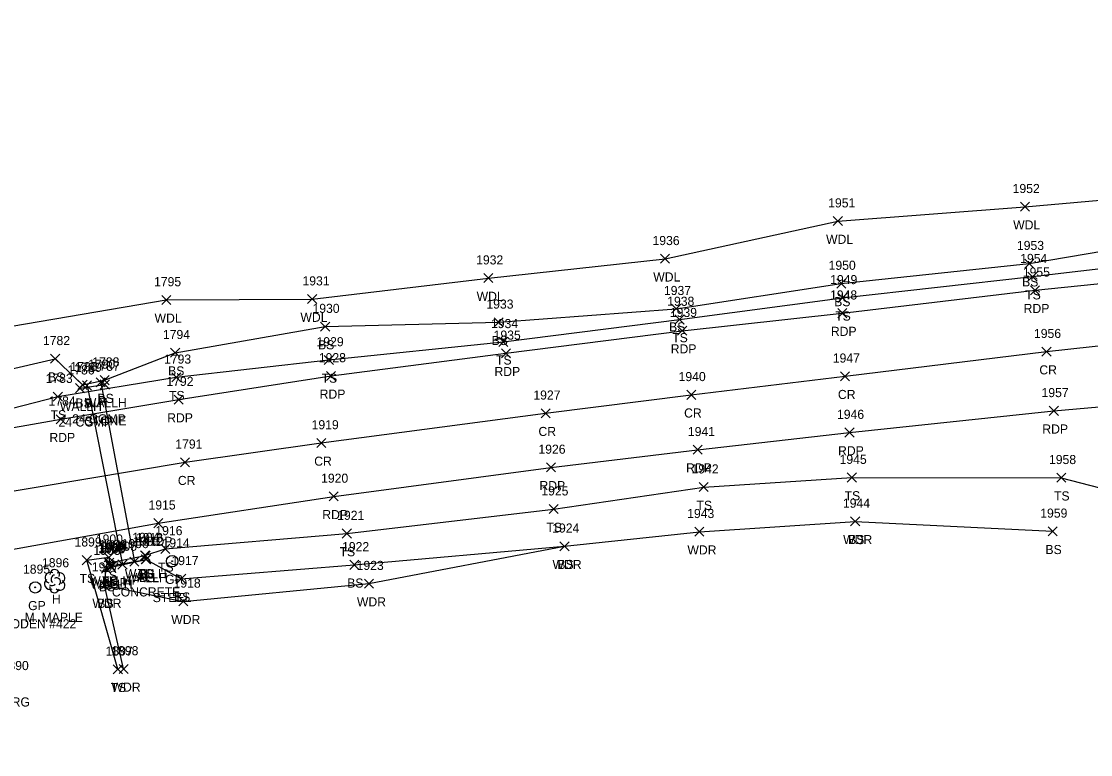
# Model space of a CAD drawing. Extents: x 1611797 to 1633212, y 298978 to 305475.
# Drawn here: x 1613918.9 to 1614153.6, y 301336.2 to 301497.2 of the extents above; entities that cross this region are included whole.
import ezdxf

# ---------------------------------------------------------------- set-up
doc = ezdxf.new("R2010")
doc.units = 0
for name, color, linetype in [('D_A', 7, 'Continuous'), ('D_C', 7, 'Continuous'), ('D_I', 7, 'Continuous'), ('D_TIC', 7, 'Continuous'), ('DCP', 7, 'Continuous'), ('DHW', 7, 'Continuous'), ('L_A', 7, 'Continuous'), ('L_C', 7, 'Continuous'), ('L_I', 7, 'Continuous'), ('L_TIC', 7, 'Continuous'), ('LAWA', 7, 'Continuous'), ('LELB', 7, 'Continuous'), ('LTD', 7, 'Continuous'), ('P_A', 7, 'Continuous'), ('P_I', 7, 'Continuous'), ('P_TIC', 7, 'Continuous'), ('PET', 7, 'Continuous'), ('PRC', 7, 'Continuous'), ('R_A', 7, 'Continuous'), ('R_C', 7, 'Continuous'), ('R_I', 7, 'Continuous'), ('RGP', 7, 'Continuous')]:
    doc.layers.add(name, color=color, linetype=linetype)

msp = doc.modelspace()

# ---------------------------------------------------------------- linework, layer by layer
at = {"layer": 'D_TIC'}
for points in [[(1613930.74, 301415.69), (1613932.74, 301417.69)], [(1613932.74, 301415.69), (1613930.74, 301417.69)], [(1613932.29, 301416.26), (1613934.29, 301418.26)], [(1613934.29, 301416.26), (1613932.29, 301418.26)], [(1613935.3, 301416.95), (1613937.3, 301418.95)], [(1613937.3, 301416.95), (1613935.3, 301418.95)], [(1613936.2, 301416.49), (1613938.2, 301418.49)], [(1613938.2, 301416.49), (1613936.2, 301418.49)], [(1613937.18, 301377.35), (1613939.18, 301379.35)], [(1613939.18, 301377.35), (1613937.18, 301379.35)], [(1613937.18, 301377.35), (1613939.18, 301379.35)], [(1613939.18, 301377.35), (1613937.18, 301379.35)], [(1613942.68, 301377.55), (1613944.68, 301379.55)], [(1613944.68, 301377.55), (1613942.68, 301379.55)], [(1613944.99, 301378.93), (1613946.99, 301380.93)], [(1613946.99, 301378.93), (1613944.99, 301380.93)], [(1613944.99, 301378.93), (1613946.99, 301380.93)], [(1613946.99, 301378.93), (1613944.99, 301380.93)], [(1613945.19, 301378.07), (1613947.19, 301380.07)], [(1613947.19, 301378.07), (1613945.19, 301380.07)], [(1613937.46, 301376.65), (1613939.46, 301378.65)], [(1613939.46, 301376.65), (1613937.46, 301378.65)], [(1613940.07, 301376.96), (1613942.07, 301378.96)], [(1613942.07, 301376.96), (1613940.07, 301378.96)]]:
    msp.add_lwpolyline(points, dxfattribs=at)
at = {"layer": 'DCP'}
for points in [[(1613933.29, 301417.26), (1613941.07, 301377.96)], [(1613936.3, 301417.95), (1613943.68, 301378.55)]]:
    msp.add_lwpolyline(points, dxfattribs=at)
at = {"layer": 'DHW'}
for points in [[(1613931.74, 301416.69), (1613937.2, 301417.49)], [(1613938.18, 301378.35), (1613938.46, 301377.65), (1613946.19, 301379.07), (1613945.99, 301379.93)], [(1613938.18, 301378.35), (1613945.99, 301379.93)]]:
    msp.add_lwpolyline(points, dxfattribs=at)
at = {"layer": 'L_TIC'}
for points in [[(1614138.15, 301455.54), (1614140.15, 301457.54)], [(1614140.15, 301455.54), (1614138.15, 301457.54)], [(1614097.09, 301452.38), (1614099.09, 301454.38)], [(1614099.09, 301452.38), (1614097.09, 301454.38)], [(1614059.15, 301444.11), (1614061.15, 301446.11)], [(1614061.15, 301444.11), (1614059.15, 301446.11)], [(1614139.09, 301443.03), (1614141.09, 301445.03)], [(1614141.09, 301443.03), (1614139.09, 301445.03)], [(1614020.38, 301439.86), (1614022.38, 301441.86)], [(1614022.38, 301439.86), (1614020.38, 301441.86)], [(1614097.84, 301438.68), (1614099.84, 301440.68)], [(1614099.84, 301438.68), (1614097.84, 301440.68)], [(1614139.8, 301440.18), (1614141.8, 301442.18)], [(1614141.8, 301440.18), (1614139.8, 301442.18)], [(1613949.68, 301435.07), (1613951.68, 301437.07)], [(1613951.68, 301435.07), (1613949.68, 301437.07)], [(1613981.7, 301435.25), (1613983.7, 301437.25)], [(1613983.7, 301435.25), (1613981.7, 301437.25)], [(1614098.1, 301435.53), (1614100.1, 301437.53)], [(1614100.1, 301435.53), (1614098.1, 301437.53)], [(1614061.6, 301433.14), (1614063.6, 301435.14)], [(1614063.6, 301433.14), (1614061.6, 301435.14)], [(1613984.55, 301429.21), (1613986.55, 301431.21)], [(1613986.55, 301429.21), (1613984.55, 301431.21)], [(1614022.64, 301430.15), (1614024.64, 301432.15)], [(1614024.64, 301430.15), (1614022.64, 301432.15)], [(1614062.32, 301430.77), (1614064.32, 301432.77)], [(1614064.32, 301430.77), (1614062.32, 301432.77)], [(1614023.64, 301425.87), (1614025.64, 301427.87)], [(1614025.64, 301425.87), (1614023.64, 301427.87)], [(1613925.3, 301422.14), (1613927.3, 301424.14)], [(1613927.3, 301422.14), (1613925.3, 301424.14)], [(1613951.64, 301423.47), (1613953.64, 301425.47)], [(1613953.64, 301423.47), (1613951.64, 301425.47)], [(1613985.36, 301421.88), (1613987.36, 301423.88)], [(1613987.36, 301421.88), (1613985.36, 301423.88)], [(1613936.13, 301417.44), (1613938.13, 301419.44)], [(1613938.13, 301417.44), (1613936.13, 301419.44)], [(1613951.87, 301418.07), (1613953.87, 301420.07)], [(1613953.87, 301418.07), (1613951.87, 301420.07)], [(1613931.29, 301416.42), (1613933.29, 301418.42)], [(1613933.29, 301416.42), (1613931.29, 301418.42)], [(1613925.88, 301413.84), (1613927.88, 301415.84)], [(1613927.88, 301413.84), (1613925.88, 301415.84)], [(1614100.16, 301396.05), (1614102.16, 301398.05)], [(1614102.16, 301396.05), (1614100.16, 301398.05)], [(1614146.12, 301396.01), (1614148.12, 301398.01)], [(1614148.12, 301396.01), (1614146.12, 301398.01)], [(1614067.65, 301393.95), (1614069.65, 301395.95)], [(1614069.65, 301393.95), (1614067.65, 301395.95)], [(1614034.69, 301389.12), (1614036.69, 301391.12)], [(1614036.69, 301389.12), (1614034.69, 301391.12)], [(1614066.7, 301384.15), (1614068.7, 301386.15)], [(1614068.7, 301384.15), (1614066.7, 301386.15)], [(1614100.89, 301386.42), (1614102.89, 301388.42)], [(1614102.89, 301386.42), (1614100.89, 301388.42)], [(1614100.89, 301386.42), (1614102.89, 301388.42)], [(1614102.89, 301386.42), (1614100.89, 301388.42)], [(1614144.21, 301384.24), (1614146.21, 301386.24)], [(1614146.21, 301384.24), (1614144.21, 301386.24)], [(1613989.31, 301383.76), (1613991.31, 301385.76)], [(1613991.31, 301383.76), (1613989.31, 301385.76)], [(1613949.46, 301380.39), (1613951.46, 301382.39)], [(1613951.46, 301380.39), (1613949.46, 301382.39)], [(1614037.09, 301380.96), (1614039.09, 301382.96)], [(1614039.09, 301380.96), (1614037.09, 301382.96)], [(1614037.09, 301380.96), (1614039.09, 301382.96)], [(1614039.09, 301380.96), (1614037.09, 301382.96)], [(1613932.24, 301377.9), (1613934.24, 301379.9)], [(1613934.24, 301377.9), (1613932.24, 301379.9)], [(1613937.07, 301378.55), (1613939.07, 301380.55)], [(1613939.07, 301378.55), (1613937.07, 301380.55)], [(1613937.1, 301377.27), (1613939.1, 301379.27)], [(1613939.1, 301377.27), (1613937.1, 301379.27)], [(1613937.18, 301377.35), (1613939.18, 301379.35)], [(1613939.18, 301377.35), (1613937.18, 301379.35)], [(1613944.99, 301378.93), (1613946.99, 301380.93)], [(1613946.99, 301378.93), (1613944.99, 301380.93)], [(1613945.13, 301378.85), (1613947.13, 301380.85)], [(1613947.13, 301378.85), (1613945.13, 301380.85)], [(1613945.26, 301378.08), (1613947.26, 301380.08)], [(1613947.26, 301378.08), (1613945.26, 301380.08)], [(1613945.26, 301378.08), (1613947.26, 301380.08)], [(1613947.26, 301378.08), (1613945.26, 301380.08)], [(1613936.45, 301376.07), (1613938.45, 301378.07)], [(1613938.45, 301376.07), (1613936.45, 301378.07)], [(1613937.2, 301376.8), (1613939.2, 301378.8)], [(1613939.2, 301376.8), (1613937.2, 301378.8)], [(1613937.56, 301376.4), (1613939.56, 301378.4)], [(1613939.56, 301376.4), (1613937.56, 301378.4)], [(1613990.95, 301376.88), (1613992.95, 301378.88)], [(1613992.95, 301376.88), (1613990.95, 301378.88)], [(1613936.1, 301372.42), (1613938.1, 301374.42)], [(1613938.1, 301372.42), (1613936.1, 301374.42)], [(1613936.1, 301372.42), (1613938.1, 301374.42)], [(1613938.1, 301372.42), (1613936.1, 301374.42)], [(1613952.94, 301373.81), (1613954.94, 301375.81)], [(1613954.94, 301373.81), (1613952.94, 301375.81)], [(1613994.15, 301372.75), (1613996.15, 301374.75)], [(1613996.15, 301372.75), (1613994.15, 301374.75)], [(1613953.4, 301368.86), (1613955.4, 301370.86)], [(1613955.4, 301368.86), (1613953.4, 301370.86)], [(1613939.05, 301353.94), (1613941.05, 301355.94)], [(1613941.05, 301353.94), (1613939.05, 301355.94)], [(1613940.3, 301354.02), (1613942.3, 301356.02)], [(1613942.3, 301354.02), (1613940.3, 301356.02)]]:
    msp.add_lwpolyline(points, dxfattribs=at)
at = {"layer": 'LAWA'}
for points in [[(1613659.39, 301379.3), (1613661.87, 301370.75), (1613686.93, 301375.42), (1613730.09, 301388.72), (1613768.03, 301396.97), (1613816.59, 301404.76), (1613861.02, 301415.83), (1613901.25, 301427.67), (1613950.68, 301436.07), (1613982.7, 301436.25), (1614021.38, 301440.86), (1614060.15, 301445.11), (1614098.09, 301453.38), (1614139.15, 301456.54), (1614173, 301459.52), (1614211.23, 301469.75), (1614243.82, 301473.03), (1614282.31, 301479.54), (1614304.52, 301484.61), (1614323.47, 301484.21), (1614343.41, 301488.74), (1614366.06, 301492.98), (1614391.26, 301497.25)], [(1613941.3, 301355.02), (1613937.1, 301373.42), (1613954.4, 301369.86), (1613995.15, 301373.75), (1614038.09, 301381.96), (1614067.7, 301385.15), (1614101.89, 301387.42)]]:
    msp.add_lwpolyline(points, dxfattribs=at)
at = {"layer": 'LELB'}
for points in [[(1613688.22, 301363.65), (1613727.18, 301373.26), (1613772.17, 301382.86), (1613812.44, 301390.94), (1613866.01, 301400.43), (1613908.89, 301410.23), (1613926.88, 301414.84), (1613952.87, 301419.07), (1613986.36, 301422.88), (1614024.64, 301426.87), (1614063.32, 301431.77), (1614099.1, 301436.53), (1614140.8, 301441.18), (1614173.87, 301445.08), (1614214.29, 301453.13), (1614246.46, 301456.83), (1614285.28, 301461.82), (1614322.04, 301468.56), (1614347.54, 301476.47), (1614359.36, 301482.63), (1614366.06, 301492.98)], [(1613687.53, 301366.74), (1613727.39, 301378.05), (1613770.58, 301387.15), (1613814.37, 301395.8), (1613864.95, 301404.5), (1613892.63, 301410.62), (1613903.75, 301417.94), (1613926.3, 301423.14), (1613932.29, 301417.42), (1613937.13, 301418.44), (1613952.64, 301424.47), (1613985.55, 301430.21), (1614023.64, 301431.15), (1614062.6, 301434.14), (1614098.84, 301439.68), (1614140.09, 301444.03), (1614173.26, 301449.68), (1614212.1, 301463.73), (1614243.82, 301473.03), (1614283.52, 301473.37), (1614303.68, 301476.17), (1614323.47, 301484.21)], [(1613945.99, 301379.93), (1613950.46, 301381.39), (1613990.31, 301384.76), (1614035.69, 301390.12), (1614068.65, 301394.95), (1614101.16, 301397.05), (1614147.12, 301397.01), (1614179.04, 301388.68)], [(1614101.89, 301387.42), (1614145.21, 301385.24)], [(1613937.1, 301373.42), (1613937.45, 301377.07), (1613938.56, 301377.4), (1613946.26, 301379.08), (1613953.94, 301374.81), (1613991.95, 301377.88), (1614038.09, 301381.96)], [(1613940.05, 301354.94), (1613933.24, 301378.9), (1613938.07, 301379.55), (1613938.18, 301378.35)], [(1613946.26, 301379.08), (1613946.13, 301379.85)], [(1613938.2, 301377.8), (1613938.1, 301378.27)]]:
    msp.add_lwpolyline(points, dxfattribs=at)
at = {"layer": 'LTD'}
msp.add_line((1613926.14, 301374.34), (1613926.14, 301374.34), dxfattribs=at)
msp.add_line((1613926.14, 301374.34), (1613926.14, 301374.34), dxfattribs=at)
msp.add_arc((1613926.19, 301375.78), 1.05, 335.5272, 180.9563, dxfattribs=at)
for centre, major_axis, ratio, start_param, end_param in [((1613925.06, 301373.64), (0.58, -1.04), 0.959034, 3.141593, 6.283185), ((1613925.35, 301375.01), (1.21, -0.51), 0.895232, 1.570796, 4.712389), ((1613925.93, 301374.8), (-0.208, -0.792), 0.645439, 3.141593, 6.283185), ((1613926.64, 301374.18), (-0.5, 0.667), 0.989748, 3.141593, 6.283185), ((1613927.14, 301373.51), (-1.09, 0.79), 0.841452, 1.570796, 4.712389), ((1613927.18, 301374.93), (-1.14, -0.48), 0.949671, 1.570796, 4.712389), ((1613926.14, 301372.84), (0.26, 1.06), 0.942809, 1.570796, 4.712389), ((1613925.68, 301373.59), (-0.625, -0.083), 0.423636, 0, 3.141593)]:
    msp.add_ellipse(centre, major_axis=major_axis, ratio=ratio, start_param=start_param, end_param=end_param, dxfattribs=at)
at = {"layer": 'P_TIC'}
for points in [[(1614140.37, 301437.19), (1614142.37, 301439.19)], [(1614142.37, 301437.19), (1614140.37, 301439.19)], [(1614098.06, 301432.16), (1614100.06, 301434.16)], [(1614100.06, 301432.16), (1614098.06, 301434.16)], [(1614062.91, 301428.31), (1614064.91, 301430.31)], [(1614064.91, 301428.31), (1614062.91, 301430.31)], [(1614024.22, 301423.34), (1614026.22, 301425.34)], [(1614026.22, 301423.34), (1614024.22, 301425.34)], [(1614142.88, 301423.7), (1614144.88, 301425.7)], [(1614144.88, 301423.7), (1614142.88, 301425.7)], [(1613985.85, 301418.38), (1613987.85, 301420.38)], [(1613987.85, 301418.38), (1613985.85, 301420.38)], [(1614098.67, 301418.3), (1614100.67, 301420.3)], [(1614100.67, 301418.3), (1614098.67, 301420.3)], [(1613952.4, 301413.17), (1613954.4, 301415.17)], [(1613954.4, 301413.17), (1613952.4, 301415.17)], [(1614064.91, 301414.23), (1614066.91, 301416.23)], [(1614066.91, 301414.23), (1614064.91, 301416.23)], [(1614032.94, 301410.17), (1614034.94, 301412.17)], [(1614034.94, 301410.17), (1614032.94, 301412.17)], [(1614144.48, 301410.71), (1614146.48, 301412.71)], [(1614146.48, 301410.71), (1614144.48, 301412.71)], [(1613926.53, 301408.86), (1613928.53, 301410.86)], [(1613928.53, 301408.86), (1613926.53, 301410.86)], [(1614099.64, 301405.94), (1614101.64, 301407.94)], [(1614101.64, 301405.94), (1614099.64, 301407.94)], [(1613983.71, 301403.65), (1613985.71, 301405.65)], [(1613985.71, 301403.65), (1613983.71, 301405.65)], [(1614066.29, 301402.16), (1614068.29, 301404.16)], [(1614068.29, 301402.16), (1614066.29, 301404.16)], [(1613953.79, 301399.41), (1613955.79, 301401.41)], [(1613955.79, 301399.41), (1613953.79, 301401.41)], [(1614034.1, 301398.28), (1614036.1, 301400.28)], [(1614036.1, 301398.28), (1614034.1, 301400.28)], [(1613986.44, 301391.91), (1613988.44, 301393.91)], [(1613988.44, 301391.91), (1613986.44, 301393.91)], [(1613947.91, 301386.03), (1613949.91, 301388.03)], [(1613949.91, 301386.03), (1613947.91, 301388.03)]]:
    msp.add_lwpolyline(points, dxfattribs=at)
at = {"layer": 'PET'}
for points in [[(1613689.79, 301361.01), (1613727.87, 301369.49), (1613773.07, 301379.01), (1613813.19, 301387.7), (1613865.89, 301398.32), (1613909.58, 301406.72), (1613927.53, 301409.86), (1613953.4, 301414.17), (1613986.85, 301419.38), (1614025.22, 301424.34), (1614063.91, 301429.31), (1614099.06, 301433.16), (1614141.37, 301438.19), (1614174.31, 301441.58), (1614214.27, 301446.57), (1614246.62, 301450.37), (1614286, 301456.17), (1614323.84, 301461.99), (1614353.18, 301466.45), (1614396.11, 301473.72)], [(1613701.72, 301336.19), (1613728.29, 301342.74), (1613750.94, 301348.22), (1613776.31, 301353.3), (1613804.99, 301359.29), (1613841.24, 301366.59), (1613881.56, 301374.47), (1613915.09, 301380.99), (1613948.91, 301387.03), (1613987.44, 301392.91), (1614035.1, 301399.28), (1614067.29, 301403.16), (1614100.64, 301406.94), (1614145.48, 301411.71), (1614172.04, 301414.07), (1614174.91, 301413.62), (1614214.97, 301418.38), (1614220.25, 301418.94), (1614228.04, 301421.41), (1614249.59, 301424.45), (1614288.66, 301429.71), (1614330.83, 301435.72), (1614357.07, 301439.35), (1614396.41, 301445)]]:
    msp.add_lwpolyline(points, dxfattribs=at)
at = {"layer": 'PRC'}
msp.add_lwpolyline([(1613693.64, 301348.14), (1613730.35, 301356.23), (1613775.18, 301366.05), (1613815.88, 301374.59), (1613867.77, 301385.2), (1613911.17, 301393.09), (1613954.79, 301400.41), (1613984.71, 301404.65), (1614033.94, 301411.17), (1614065.91, 301415.23), (1614099.67, 301419.3), (1614143.88, 301424.7), (1614174.58, 301428.12), (1614215.56, 301433.27), (1614248.59, 301437.14), (1614287.59, 301442.54), (1614326.75, 301448.33), (1614363.42, 301453.92), (1614394.65, 301458.77)], dxfattribs=at)
at = {"layer": 'RGP'}
for p, q in [((1613951.98, 301378.69), (1613951.98, 301378.69)), ((1613921.92, 301372.93), (1613921.92, 301372.93))]:
    msp.add_line(p, q, dxfattribs=at)
for centre, radius in [((1613951.98, 301378.69), 1.25), ((1613951.98, 301378.69), 0.0833), ((1613921.92, 301372.93), 1.25), ((1613921.92, 301372.93), 0.0833)]:
    msp.add_circle(centre, radius, dxfattribs=at)

# ---------------------------------------------------------------- texts
at = {"layer": 'D_A'}
for s, p in [('WALLH', (1613932.79, 301412.49)), ('P', (1613935.67, 301412.95)), ('WALLH', (1613927.33, 301411.69)), ('P', (1613932.67, 301412.26)), ('WALLH', (1613941.58, 301374.93)), ('WALLH', (1613941.58, 301374.93)), ('WALLH', (1613933.77, 301373.35)), ('WALLH', (1613933.77, 301373.35)), ('WALLH', (1613934.05, 301372.65)), ('P', (1613940.45, 301372.96)), ('WALLH', (1613941.78, 301374.07)), ('P', (1613943.06, 301373.55))]:
    msp.add_text(s, height=2, dxfattribs=at).set_placement(p)
at = {"layer": 'D_C'}
for s, p in [('24 CGMP', (1613927.02, 301408.26)), ('24 CGMP', (1613930.02, 301408.95)), ('STONE', (1613932.74, 301408.49)), ('CONCRETE', (1613938.74, 301370.93)), ('CONCRETE', (1613938.74, 301370.93))]:
    msp.add_text(s, height=2, dxfattribs=at).set_placement(p)
at = {"layer": 'D_I'}
for s, p in [('1786', (1613928.99, 301419.69)), ('1789', (1613930.59, 301420.26)), ('1790', (1613933.52, 301420.95)), ('1787', (1613934.51, 301420.49)), ('1904', (1613943.22, 301382.93)), ('1904', (1613943.22, 301382.93)), ('1903', (1613943.42, 301382.07)), ('1902', (1613935.69, 301380.65)), ('1901', (1613935.98, 301381.35)), ('1901', (1613935.98, 301381.35)), ('1905', (1613938.3, 301380.96)), ('1906', (1613940.86, 301381.55))]:
    msp.add_text(s, height=2, dxfattribs=at).set_placement(p)
at = {"layer": 'L_A'}
for s, p in [('WDL', (1614136.56, 301451.54)), ('WDL', (1614095.5, 301448.38)), ('WDL', (1614057.56, 301440.11)), ('BS', (1614138.53, 301439.03)), ('WDL', (1614018.8, 301435.86)), ('TS', (1614139.21, 301436.18)), ('BS', (1614097.28, 301434.68)), ('WDL', (1613980.12, 301431.25)), ('TS', (1614097.51, 301431.53)), ('WDL', (1613948.1, 301431.07)), ('BS', (1614061.04, 301429.14)), ('TS', (1614061.73, 301426.77)), ('BS', (1613983.99, 301425.21)), ('BS', (1614022.08, 301426.15)), ('TS', (1614023.05, 301421.87)), ('BS', (1613951.08, 301419.47)), ('BS', (1613924.74, 301418.14)), ('TS', (1613984.77, 301417.88)), ('BS', (1613930.73, 301412.42)), ('BS', (1613935.57, 301413.44)), ('TS', (1613951.28, 301414.07)), ('TS', (1613925.29, 301409.84)), ('TS', (1614099.57, 301392.05)), ('TS', (1614145.53, 301392.01)), ('TS', (1614067.06, 301389.95)), ('TS', (1614034.1, 301385.12)), ('WDR', (1614099.25, 301382.42)), ('BS', (1614100.33, 301382.42)), ('TS', (1613988.72, 301379.76)), ('WDR', (1614065.06, 301380.15)), ('BS', (1614143.65, 301380.24)), ('TS', (1613944.4, 301374.93)), ('BS', (1613944.58, 301374.85)), ('TS', (1613948.87, 301376.39)), ('WDR', (1614035.45, 301376.96)), ('BS', (1614036.53, 301376.96)), ('TS', (1613931.65, 301373.9)), ('TS', (1613936.48, 301374.55)), ('TS', (1613936.59, 301373.35)), ('BS', (1613936.54, 301373.27)), ('BS', (1613936.64, 301372.8)), ('BS', (1613937, 301372.4)), ('BS', (1613944.7, 301374.08)), ('BS', (1613944.7, 301374.08)), ('BS', (1613990.39, 301372.88)), ('BS', (1613935.89, 301372.07)), ('H', (1613925.58, 301369.34)), ('WDR', (1613934.46, 301368.42)), ('BS', (1613935.54, 301368.42)), ('BS', (1613952.38, 301369.81)), ('WDR', (1613992.52, 301368.75)), ('WDR', (1613951.76, 301364.86)), ('TS', (1613938.46, 301349.94)), ('WDR', (1613938.66, 301350.02))]:
    msp.add_text(s, height=2, dxfattribs=at).set_placement(p)
at = {"layer": 'L_C'}
msp.add_text('M. MAPLE', height=2, dxfattribs=at).set_placement((1613919.59, 301365.34))
at = {"layer": 'L_I'}
for s, p in [('1952', (1614136.45, 301459.54)), ('1951', (1614095.96, 301456.38)), ('1936', (1614057.4, 301448.11)), ('1953', (1614137.39, 301447.03)), ('1932', (1614018.69, 301443.86)), ('1954', (1614138.11, 301444.18)), ('1950', (1614096.06, 301442.68)), ('1795', (1613947.99, 301439.07)), ('1931', (1613980.57, 301439.25)), ('1949', (1614096.4, 301439.53)), ('1937', (1614059.91, 301437.14)), ('1933', (1614020.94, 301434.15)), ('1938', (1614060.63, 301434.77)), ('1930', (1613982.77, 301433.21)), ('1934', (1614021.95, 301429.87)), ('1794', (1613949.94, 301427.47)), ('1782', (1613923.61, 301426.14)), ('1929', (1613983.66, 301425.88)), ('1793', (1613950.18, 301422.07)), ('1785', (1613929.6, 301420.42)), ('1788', (1613934.44, 301421.44)), ('1783', (1613924.19, 301417.84)), ('1945', (1614098.47, 301400.05)), ('1958', (1614144.43, 301400.01)), ('1942', (1614065.96, 301397.95)), ('1925', (1614033, 301393.12)), ('1944', (1614099.2, 301390.42)), ('1944', (1614099.2, 301390.42)), ('1921', (1613988.19, 301387.76)), ('1943', (1614065.01, 301388.15)), ('1959', (1614142.51, 301388.24)), ('1916', (1613948.28, 301384.39)), ('1924', (1614035.39, 301384.96)), ('1924', (1614035.39, 301384.96)), ('1899', (1613930.54, 301381.9)), ('1900', (1613935.21, 301382.55)), ('1904', (1613943.22, 301382.93)), ('1913', (1613944.01, 301382.85)), ('1912', (1613944.13, 301382.08)), ('1912', (1613944.13, 301382.08)), ('1908', (1613934.68, 301380.07)), ('1909', (1613935.78, 301380.4)), ('1901', (1613935.98, 301381.35)), ('1910', (1613935.99, 301380.8)), ('1911', (1613936.54, 301381.27)), ('1922', (1613989.26, 301380.88)), ('1896', (1613923.4, 301377.34)), ('1917', (1613951.81, 301377.81)), ('1907', (1613934.33, 301376.42)), ('1907', (1613934.33, 301376.42)), ('1923', (1613992.46, 301376.75)), ('1918', (1613952.28, 301372.86)), ('1897', (1613937.36, 301357.94)), ('1898', (1613938.61, 301358.02))]:
    msp.add_text(s, height=2, dxfattribs=at).set_placement(p)
at = {"layer": 'P_A'}
for s, p in [('RDP', (1614138.86, 301433.19)), ('RDP', (1614096.55, 301428.16)), ('RDP', (1614061.4, 301424.31)), ('RDP', (1614022.71, 301419.34)), ('CR', (1614142.31, 301419.7)), ('RDP', (1613984.34, 301414.38)), ('CR', (1614098.1, 301414.3)), ('CR', (1614064.34, 301410.23)), ('RDP', (1613950.88, 301409.17)), ('CR', (1614032.37, 301406.17)), ('RDP', (1614142.97, 301406.71)), ('RDP', (1613925.02, 301404.86)), ('RDP', (1614098.13, 301401.94)), ('CR', (1613983.15, 301399.65)), ('RDP', (1614064.78, 301398.16)), ('CR', (1613953.22, 301395.41)), ('RDP', (1614032.59, 301394.28)), ('RDP', (1613984.93, 301387.91)), ('RDP', (1613946.39, 301382.03))]:
    msp.add_text(s, height=2, dxfattribs=at).set_placement(p)
at = {"layer": 'P_I'}
for s, p in [('1955', (1614138.68, 301441.19)), ('1948', (1614096.37, 301436.16)), ('1939', (1614061.21, 301432.31)), ('1935', (1614022.53, 301427.34)), ('1956', (1614141.13, 301427.7)), ('1928', (1613984.16, 301422.38)), ('1947', (1614096.97, 301422.3)), ('1792', (1613950.7, 301417.17)), ('1940', (1614063.13, 301418.23)), ('1957', (1614142.79, 301414.71)), ('1784', (1613924.84, 301412.86)), ('1927', (1614031.25, 301414.17)), ('1946', (1614097.9, 301409.94)), ('1919', (1613982.58, 301407.65)), ('1941', (1614065.17, 301406.16)), ('1791', (1613952.66, 301403.41)), ('1926', (1614032.36, 301402.28)), ('1920', (1613984.66, 301395.91)), ('1915', (1613946.78, 301390.03))]:
    msp.add_text(s, height=2, dxfattribs=at).set_placement(p)
at = {"layer": 'R_A'}
for s, p in [('GP', (1613950.42, 301373.69)), ('GP', (1613920.35, 301367.93)), ('DRG', (1613914.81, 301346.76))]:
    msp.add_text(s, height=2, dxfattribs=at).set_placement(p)
at = {"layer": 'R_C'}
for s, p in [('STEEL', (1613947.7, 301369.69)), ('WOODEN #422', (1613911.9, 301363.93))]:
    msp.add_text(s, height=2, dxfattribs=at).set_placement(p)
at = {"layer": 'R_I'}
for s, p in [('1914', (1613949.86, 301381.69)), ('1895', (1613919.23, 301375.93)), ('1890', (1613914.54, 301354.76))]:
    msp.add_text(s, height=2, dxfattribs=at).set_placement(p)

doc.saveas('drawing.dxf')
